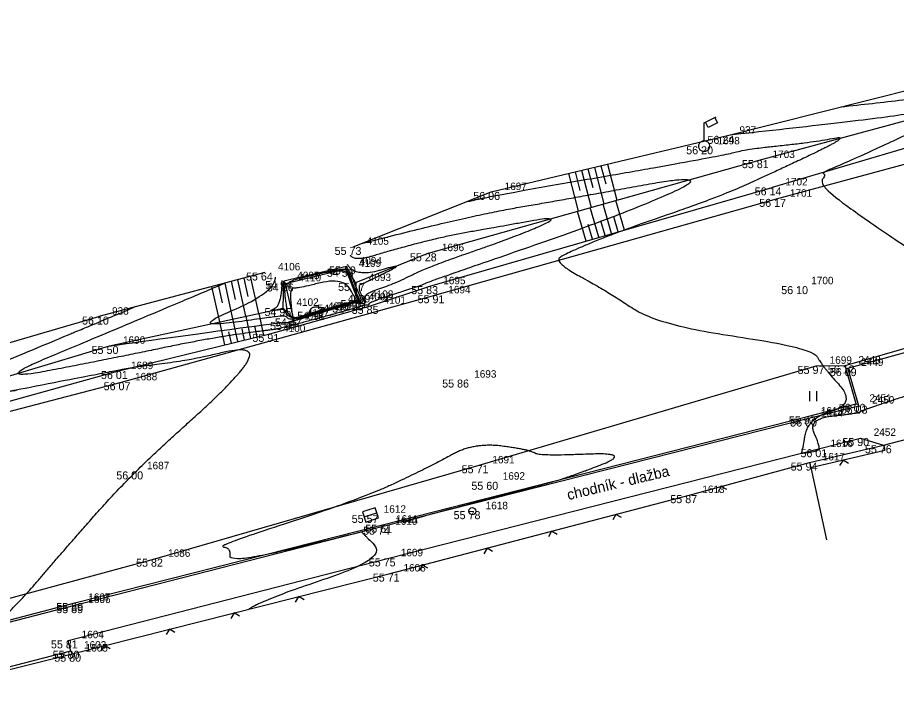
# Model space of a CAD drawing. Extents: x -704017 to -701500, y -1008977 to -1008450.
# Drawn here: x -702683.67 to -702650.74, y -1008782.68 to -1008757.4 of the extents above; entities that cross this region are included whole.
import ezdxf

# ---------------------------------------------------------------- set-up
doc = ezdxf.new("R2010")
doc.units = 0
for name, color, linetype in [('Z_bet_konstrukce', 7, 'Continuous'), ('Z_body', 7, 'Continuous'), ('Z_body_cisla', 7, 'Continuous'), ('Z_body_vysky', 7, 'Continuous'), ('Z_chodnik', 7, 'Continuous'), ('Z_komunikace', 7, 'Continuous'), ('Z_obruby', 7, 'Continuous'), ('Z_oploceni', 7, 'Continuous'), ('Z_popis', 7, 'Continuous'), ('Z_site_znaky_kanalizace', 7, 'Continuous'), ('Z_site_znaky_plynovod', 7, 'Continuous'), ('Z_site_znaky_VO', 7, 'Continuous'), ('Z_teren_hrany_paty', 7, 'Continuous'), ('Z_vrstevnice_hlavni', 7, 'Continuous'), ('Z_vrstevnice_vedlejsi', 7, 'Continuous'), ('Z_vstupy', 7, 'Continuous')]:
    doc.layers.add(name, color=color, linetype=linetype)

# ---------------------------------------------------------------- blocks, each defined once
blk = doc.blocks.new('POINT_DISPLAY')
blk.add_line((0, 0), (0, 0))
blk = doc.blocks.new('Z212')
for p, q in [((-0.17, 0.17), (0, 0)), ((0, 0), (0.17, 0.17))]:
    blk.add_line(p, q)
blk = doc.blocks.new('Z306')
for p, q in [((-0.13, 0.17), (-0.13, -0.2)), ((0.13, 0.17), (0.13, -0.2))]:
    blk.add_line(p, q)
blk = doc.blocks.new('Z13')
for p, q in [((0, 0.88), (0.45, 1.1)), ((0.4, 1.07), (0.5, 0.88)), ((0, 0.2), (0, 0.88)), ((0.15, 0.7), (0.05, 0.9)), ((0.5, 0.88), (0.15, 0.7)), ((-0.2, 0.05), (-0.15, 0.15)), ((-0.2, -0.05), (-0.2, 0.05)), ((-0.15, 0.15), (-0.05, 0.2)), ((-0.05, 0.2), (0.05, 0.2)), ((0.05, 0.2), (0.15, 0.15)), ((0.15, 0.15), (0.2, 0.05)), ((0.2, 0.05), (0.2, -0.05)), ((-0.15, -0.15), (-0.2, -0.05)), ((-0.05, -0.2), (-0.15, -0.15)), ((0.05, -0.2), (-0.05, -0.2)), ((0.15, -0.15), (0.05, -0.2)), ((0.2, -0.05), (0.15, -0.15))]:
    blk.add_line(p, q)
blk = doc.blocks.new('Z38')
for p, q in [((0.25, 0.2), (-0.25, 0.2)), ((-0.25, 0.2), (-0.25, -0.2)), ((-0.25, 0), (0.25, 0)), ((0.25, -0.2), (0.25, 0.2)), ((-0.25, -0.2), (0.25, -0.2))]:
    blk.add_line(p, q)
blk = doc.blocks.new('Z614')
for p, q in [((-0.13, 0.03), (-0.1, 0.08)), ((-0.13, -0.03), (-0.13, 0.03)), ((-0.1, 0.08), (-0.08, 0.1)), ((-0.08, 0.1), (-0.03, 0.13)), ((-0.03, 0.13), (0.03, 0.13)), ((0.03, 0.13), (0.08, 0.1)), ((0.08, 0.1), (0.1, 0.08)), ((0.1, 0.08), (0.13, 0.03)), ((0.13, 0.03), (0.13, -0.03)), ((-0.1, -0.08), (-0.13, -0.03)), ((-0.08, -0.1), (-0.1, -0.08)), ((-0.03, -0.13), (-0.08, -0.1)), ((0.03, -0.13), (-0.03, -0.13)), ((0.08, -0.1), (0.03, -0.13)), ((0.1, -0.08), (0.08, -0.1)), ((0.13, -0.03), (0.1, -0.08))]:
    blk.add_line(p, q)

msp = doc.modelspace()

# ---------------------------------------------------------------- linework, layer by layer
at = {"layer": 'Z_bet_konstrukce'}
for p, q in [((-702673.51, -1008768.8), (-702671.01, -1008768.07)), ((-702671.01, -1008768.07), (-702670.94, -1008768.34)), ((-702673.51, -1008768.8), (-702673.44, -1008769.03))]:
    msp.add_line(p, q, dxfattribs=at)
at = {"layer": 'Z_chodnik'}
for p, q in [((-702652.15, -1008771.94), (-702652.56, -1008770.53)), ((-702654.07, -1008772.42), (-702652.15, -1008771.94)), ((-702670.02, -1008776.47), (-702654.07, -1008772.42)), ((-702653.71, -1008773.57), (-702652.09, -1008773.15)), ((-702652.09, -1008773.15), (-702651.22, -1008773.42)), ((-702669.81, -1008777.66), (-702653.71, -1008773.57)), ((-702681.52, -1008779.41), (-702670.02, -1008776.47)), ((-702681.77, -1008780.73), (-702669.81, -1008777.66)), ((-702686.34, -1008780.66), (-702681.52, -1008779.41)), ((-702681.68, -1008781.12), (-702681.77, -1008780.73)), ((-702685.78, -1008782.18), (-702681.68, -1008781.12)), ((-702681.62, -1008781.23), (-702681.68, -1008781.12))]:
    msp.add_line(p, q, dxfattribs=at)
at = {"layer": 'Z_komunikace'}
for p, q in [((-702655.23, -1008764.19), (-702640.07, -1008760.08)), ((-702668.03, -1008767.8), (-702655.23, -1008764.19)), ((-702679.77, -1008771.06), (-702668.03, -1008767.8)), ((-702652.66, -1008770.43), (-702648.22, -1008769.16)), ((-702666.38, -1008774.17), (-702653.74, -1008770.45)), ((-702653.74, -1008770.45), (-702652.66, -1008770.43)), ((-702689.14, -1008773.5), (-702679.77, -1008771.06)), ((-702678.53, -1008777.67), (-702666.38, -1008774.17)), ((-702687.56, -1008780.13), (-702678.53, -1008777.67))]:
    msp.add_line(p, q, dxfattribs=at)
at = {"layer": 'Z_obruby'}
for p, q in [((-702652.56, -1008770.53), (-702648.67, -1008769.46)), ((-702652.25, -1008771.87), (-702652.66, -1008770.43)), ((-702654.07, -1008772.34), (-702652.25, -1008771.87)), ((-702669.99, -1008776.4), (-702654.07, -1008772.34)), ((-702681.52, -1008779.33), (-702669.99, -1008776.4)), ((-702686.34, -1008780.58), (-702681.52, -1008779.33))]:
    msp.add_line(p, q, dxfattribs=at)
at = {"layer": 'Z_oploceni'}
for p, q in [((-702654, -1008774.07), (-702651.22, -1008773.42)), ((-702651.22, -1008773.42), (-702651.17, -1008773.61)), ((-702653.95, -1008774.26), (-702651.17, -1008773.61)), ((-702658.51, -1008775.29), (-702654, -1008774.07)), ((-702654, -1008774.07), (-702653.95, -1008774.26)), ((-702653.95, -1008774.26), (-702653.36, -1008776.97)), ((-702669.71, -1008778.23), (-702658.51, -1008775.29)), ((-702681.62, -1008781.23), (-702669.71, -1008778.23))]:
    msp.add_line(p, q, dxfattribs=at)
at = {"layer": 'Z_teren_hrany_paty'}
for p, q in [((-702657.12, -1008761.83), (-702639.57, -1008757.4)), ((-702655.88, -1008762.74), (-702639.67, -1008758.35)), ((-702639.01, -1008758.94), (-702655.4, -1008763.76)), ((-702665.92, -1008763.93), (-702657.12, -1008761.83)), ((-702668.27, -1008766.23), (-702655.88, -1008762.74)), ((-702661.57, -1008762.89), (-702661.22, -1008764.24)), ((-702663.03, -1008763.24), (-702662.66, -1008764.65)), ((-702662.78, -1008763.18), (-702662.6, -1008763.88)), ((-702662.54, -1008763.12), (-702662.18, -1008764.51)), ((-702662.3, -1008763.07), (-702662.12, -1008763.76)), ((-702662.05, -1008763.01), (-702661.7, -1008764.38)), ((-702661.81, -1008762.95), (-702661.63, -1008763.63)), ((-702671.09, -1008765.99), (-702665.92, -1008763.93)), ((-702668.22, -1008767.46), (-702655.4, -1008763.76)), ((-702660.93, -1008765.36), (-702661.25, -1008764.25)), ((-702661.89, -1008765.63), (-702662.21, -1008764.52)), ((-702661.41, -1008765.49), (-702661.73, -1008764.39)), ((-702662.37, -1008765.77), (-702662.69, -1008764.66)), ((-702661.17, -1008765.43), (-702661.33, -1008764.87)), ((-702662.13, -1008765.7), (-702662.29, -1008765.15)), ((-702661.65, -1008765.56), (-702661.81, -1008765.01)), ((-702668.27, -1008766.23), (-702671.01, -1008767.34)), ((-702671.35, -1008766.72), (-702673.69, -1008767.27)), ((-702673.63, -1008767.36), (-702671.38, -1008766.81)), ((-702671.38, -1008766.81), (-702671.35, -1008766.72)), ((-702671.38, -1008766.81), (-702670.92, -1008767.98)), ((-702671.01, -1008767.34), (-702671.35, -1008766.72)), ((-702674.41, -1008766.95), (-702680.63, -1008768.6)), ((-702675.43, -1008767.22), (-702675.13, -1008768.59)), ((-702675.19, -1008767.16), (-702675.04, -1008767.85)), ((-702674.95, -1008767.09), (-702674.64, -1008768.48)), ((-702676.4, -1008767.48), (-702676.11, -1008768.8)), ((-702676.15, -1008767.41), (-702676.01, -1008768.08)), ((-702675.91, -1008767.35), (-702675.62, -1008768.69)), ((-702675.67, -1008767.28), (-702675.52, -1008767.96)), ((-702673.72, -1008768.28), (-702673.69, -1008767.27)), ((-702673.63, -1008767.36), (-702673.69, -1008767.27)), ((-702673.33, -1008768.67), (-702673.63, -1008767.36)), ((-702670.92, -1008767.98), (-702671.01, -1008767.34)), ((-702670.45, -1008768.2), (-702668.22, -1008767.46)), ((-702674.22, -1008769.25), (-702670.45, -1008768.2)), ((-702670.92, -1008767.98), (-702673.33, -1008768.67)), ((-702680.22, -1008769.7), (-702673.72, -1008768.28)), ((-702674.44, -1008769.3), (-702674.62, -1008768.48)), ((-702673.33, -1008768.67), (-702673.72, -1008768.28)), ((-702689.43, -1008771.17), (-702680.63, -1008768.6)), ((-702675.9, -1008769.66), (-702676.09, -1008768.8)), ((-702675.42, -1008769.54), (-702675.6, -1008768.69)), ((-702674.93, -1008769.42), (-702675.11, -1008768.58)), ((-702675.66, -1008769.6), (-702675.75, -1008769.17)), ((-702675.17, -1008769.48), (-702675.26, -1008769.06)), ((-702674.69, -1008769.36), (-702674.78, -1008768.95)), ((-702679.92, -1008770.64), (-702674.22, -1008769.25)), ((-702688.98, -1008772.33), (-702680.22, -1008769.7)), ((-702688.82, -1008773.11), (-702679.92, -1008770.64))]:
    msp.add_line(p, q, dxfattribs=at)
at = {"layer": 'Z_vrstevnice_hlavni'}
for points in [[(-702666.86, -1008764.305), (-702666.101, -1008764.107), (-702660.186, -1008763.092), (-702656.884, -1008762.487), (-702656.428, -1008762.338), (-702653.8, -1008762.059), (-702652.34, -1008761.781), (-702655.604, -1008763.327), (-702657.495, -1008764.162), (-702661.19, -1008765.431), (-702663.088, -1008766.219), (-702663.599, -1008766.55), (-702661.588, -1008767.639), (-702659.693, -1008768.918), (-702653.899, -1008769.76), (-702653.524, -1008770.446), (-702652.25, -1008771.87), (-702654.07, -1008772.42), (-702654.272, -1008773.671), (-702654.329, -1008773.727), (-702654.053, -1008773.693), (-702653.751, -1008773.641), (-702653.563, -1008773.532), (-702654.07, -1008772.42), (-702652.136, -1008772.219), (-702652.047, -1008772.104), (-702648.446, -1008770.943), (-702648.305, -1008770.957), (-702647.465, -1008771.9), (-702647.268, -1008772.215), (-702647.277, -1008772.427)], [(-702673.128, -1008767.138), (-702671.359, -1008766.747), (-702671.113, -1008767.192), (-702670.987, -1008767.505), (-702670.748, -1008768.06), (-702670.962, -1008768.022), (-702672.191, -1008768.376), (-702673.425, -1008768.739), (-702673.7, -1008768.33), (-702673.746, -1008768.331), (-702674.311, -1008768.409), (-702673.77, -1008768.184), (-702673.752, -1008767.243)], [(-702687.525, -1008782.68), (-702687.628, -1008782.663), (-702687.511, -1008782.409), (-702686.258, -1008780.875), (-702685.545, -1008780.672), (-702685.055, -1008780.327), (-702684.466, -1008780.125), (-702684.466, -1008780.094), (-702683.981, -1008779.656), (-702683.311, -1008778.972), (-702681.946, -1008777.366), (-702679.32, -1008774.4), (-702675.533, -1008771.027), (-702674.634, -1008769.634), (-702677.342, -1008770.268), (-702679.35, -1008770.501), (-702679.926, -1008770.622), (-702682.94, -1008771.203), (-702688.968, -1008772.388), (-702689.155, -1008772.391), (-702689.011, -1008772.25), (-702687.588, -1008771.708), (-702680.562, -1008768.783), (-702679.278, -1008768.241)]]:
    msp.add_open_spline(points, degree=2, dxfattribs=at)
at = {"layer": 'Z_vrstevnice_vedlejsi'}
for points in [[(-702652.815, -1008760.743), (-702648.327, -1008760.267), (-702643.024, -1008759.258), (-702644.913, -1008760.153), (-702649.44, -1008762.007), (-702648.751, -1008762.164), (-702648.976, -1008762.495), (-702644.741, -1008765.284), (-702643.699, -1008766.374), (-702642.5, -1008767.662), (-702642.564, -1008767.76), (-702643.4, -1008768.055), (-702640.02, -1008769.28), (-702639.841, -1008769.293), (-702639.855, -1008769.324), (-702639.96, -1008769.53), (-702640.699, -1008770.697), (-702640.984, -1008770.85)], [(-702656.954, -1008761.788), (-702651.064, -1008761.163), (-702647.682, -1008760.52), (-702652.196, -1008762.658), (-702653.579, -1008763.224), (-702653.368, -1008763.272), (-702653.714, -1008763.779), (-702647.226, -1008768.053), (-702646.928, -1008768.364), (-702646.586, -1008768.732), (-702646.604, -1008768.76), (-702648.215, -1008769.328), (-702647.964, -1008769.419), (-702644.239, -1008770.04), (-702644.145, -1008770.05), (-702644.165, -1008770.085), (-702645.298, -1008771.374), (-702645.396, -1008771.53), (-702645.789, -1008771.741), (-702645.803, -1008772.093)], [(-702670.777, -1008765.865), (-702666.854, -1008764.844), (-702662.993, -1008764.181), (-702657.283, -1008763.135), (-702661.236, -1008764.88), (-702668.227, -1008767.281), (-702668.558, -1008767.445), (-702670.532, -1008768.074), (-702670.485, -1008768.184), (-702670.637, -1008768.157), (-702671.255, -1008768.358), (-702673.962, -1008769.086), (-702674.137, -1008769.088), (-702676.561, -1008769.426), (-702680.073, -1008770.161), (-702684.783, -1008771.07), (-702680.391, -1008769.242), (-702675.897, -1008767.345)], [(-702680.22, -1008769.7), (-702674.006, -1008768.836), (-702673.558, -1008768.831), (-702673.268, -1008768.753), (-702672.573, -1008768.526), (-702671.117, -1008768.098), (-702671.006, -1008768.066), (-702670.573, -1008768.143), (-702670.738, -1008767.757), (-702669.615, -1008767.4), (-702668.25, -1008766.722), (-702664.978, -1008765.598), (-702663.127, -1008764.781), (-702665.8, -1008765.271), (-702667.607, -1008765.581), (-702669.649, -1008766.113), (-702671.057, -1008766.544), (-702671.201, -1008766.301)], [(-702671.321, -1008766.639), (-702671.021, -1008767.147), (-702669.017, -1008766.533), (-702670.672, -1008767.355), (-702670.944, -1008767.441), (-702670.66, -1008768.101), (-702670.984, -1008768.044), (-702671.654, -1008768.237), (-702673.47, -1008768.771), (-702673.599, -1008768.58), (-702673.876, -1008768.583), (-702677.265, -1008769.055), (-702674.02, -1008767.702), (-702674.009, -1008767.128)], [(-702673.558, -1008768.443), (-702673.674, -1008767.808), (-702673.66, -1008767.315), (-702672.535, -1008767.04), (-702671.371, -1008766.783), (-702671.265, -1008766.975), (-702670.953, -1008767.747), (-702670.836, -1008768.019), (-702670.941, -1008768.001), (-702672.729, -1008768.514), (-702673.38, -1008768.706), (-702673.558, -1008768.443)], [(-702673.354, -1008768.646), (-702673.43, -1008768.233), (-702673.458, -1008767.527), (-702673.188, -1008767.55), (-702671.478, -1008767.132), (-702670.964, -1008767.989), (-702670.969, -1008767.993), (-702671.523, -1008768.153), (-702673.266, -1008768.653), (-702673.335, -1008768.674), (-702673.354, -1008768.646)], [(-702672.731, -1008768.48), (-702672.741, -1008768.225), (-702672.136, -1008768.275), (-702672.196, -1008768.327), (-702672.731, -1008768.48)], [(-702669.172, -1008776.325), (-702669.407, -1008776.314), (-702664.275, -1008774.971), (-702663.025, -1008774.624), (-702660.572, -1008773.676), (-702664.142, -1008773.837), (-702664.435, -1008773.598), (-702666.561, -1008773.314), (-702668.165, -1008774.202), (-702670.798, -1008775.443), (-702676.268, -1008777.211), (-702675.683, -1008777.247), (-702675.755, -1008777.865), (-702670.787, -1008776.661), (-702670.787, -1008776.666), (-702669.81, -1008777.66), (-702674.534, -1008779.23), (-702675.003, -1008779.563)]]:
    msp.add_open_spline(points, degree=2, dxfattribs=at)
at = {"layer": 'Z_vstupy'}
for p, q in [((-702651.22, -1008773.42), (-702648.22, -1008772.64)), ((-702685.75, -1008782.26), (-702681.62, -1008781.23))]:
    msp.add_line(p, q, dxfattribs=at)

# ---------------------------------------------------------------- block references
at = {"layer": 'Z_body'}
for p in [(-702657.12, -1008761.83), (-702657.94, -1008762.22), (-702655.88, -1008762.74), (-702665.92, -1008763.93), (-702655.4, -1008763.76), (-702655.23, -1008764.19), (-702671.09, -1008765.99), (-702668.27, -1008766.23), (-702671.38, -1008766.81), (-702671.35, -1008766.72), (-702674.41, -1008766.95), (-702673.69, -1008767.27), (-702673.63, -1008767.36), (-702671.01, -1008767.34), (-702668.22, -1008767.46), (-702654.43, -1008767.46), (-702668.03, -1008767.8), (-702671.79, -1008768.15), (-702671.01, -1008768.07), (-702670.92, -1008767.98), (-702670.45, -1008768.2), (-702673.72, -1008768.28), (-702672.54, -1008768.42), (-702680.63, -1008768.6), (-702673.51, -1008768.8), (-702673.33, -1008768.67), (-702674.22, -1008769.25), (-702680.22, -1008769.7), (-702653.74, -1008770.45), (-702652.66, -1008770.43), (-702679.92, -1008770.64), (-702652.56, -1008770.53), (-702679.77, -1008771.06), (-702667.06, -1008770.96), (-702652.25, -1008771.87), (-702652.15, -1008771.94), (-702654.07, -1008772.34), (-702654.07, -1008772.42), (-702652.09, -1008773.15), (-702651.22, -1008773.42), (-702653.71, -1008773.57), (-702654, -1008774.07), (-702679.32, -1008774.4), (-702666.38, -1008774.17), (-702665.99, -1008774.79), (-702658.51, -1008775.29), (-702670.45, -1008776.03), (-702666.63, -1008775.89), (-702669.99, -1008776.4), (-702670.02, -1008776.47), (-702678.53, -1008777.67), (-702669.81, -1008777.66), (-702669.71, -1008778.23), (-702681.52, -1008779.33), (-702681.52, -1008779.41), (-702681.77, -1008780.73), (-702681.68, -1008781.12), (-702681.62, -1008781.23)]:
    msp.add_blockref('POINT_DISPLAY', p, dxfattribs=at)
at = {"layer": 'Z_oploceni'}
for p, rotation in [((-702652.74, -1008773.98), -166.80000000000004), ((-702657.3, -1008774.96), -164.90000000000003), ((-702661.25, -1008776.01), -165.3), ((-702663.66, -1008776.64), -165.3), ((-702666.08, -1008777.28), -165.3), ((-702668.5, -1008777.91), -165.3), ((-702673.14, -1008779.09), -165.9), ((-702675.56, -1008779.7), -165.9), ((-702677.98, -1008780.31), -165.9), ((-702680.41, -1008780.92), -165.9)]:
    msp.add_blockref('Z212', p, dxfattribs=dict(at, rotation=rotation))
at = {"layer": 'Z_popis'}
msp.add_blockref('Z306', (-702653.86, -1008771.57), dxfattribs=at)
at = {"layer": 'Z_site_znaky_kanalizace', "rotation": 18}
msp.add_blockref('Z38', (-702670.45, -1008776.03), dxfattribs=at)
at = {"layer": 'Z_site_znaky_plynovod', "rotation": 10.799999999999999}
msp.add_blockref('Z614', (-702666.63, -1008775.89), dxfattribs=at)
at = {"layer": 'Z_site_znaky_VO'}
msp.add_blockref('Z13', (-702657.94, -1008762.22), dxfattribs=at)

# ---------------------------------------------------------------- texts
at = {"layer": 'Z_body_cisla'}
for s, p in [('937', (-702656.62, -1008761.75)), ('1698', (-702657.44, -1008762.15)), ('1703', (-702655.38, -1008762.66)), ('1697', (-702665.42, -1008763.86)), ('1702', (-702654.9, -1008763.69)), ('1701', (-702654.73, -1008764.11)), ('4105', (-702670.59, -1008765.91)), ('1696', (-702667.77, -1008766.15)), ('4109', (-702670.88, -1008766.74)), ('4094', (-702670.85, -1008766.65)), ('4106', (-702673.91, -1008766.87)), ('4095', (-702673.19, -1008767.2)), ('4110', (-702673.13, -1008767.28)), ('4093', (-702670.51, -1008767.27)), ('1695', (-702667.72, -1008767.39)), ('1700', (-702653.93, -1008767.39)), ('1694', (-702667.53, -1008767.73)), ('4099', (-702671.29, -1008768.07)), ('4092', (-702670.51, -1008767.99)), ('4108', (-702670.42, -1008767.9)), ('4101', (-702669.95, -1008768.12)), ('4102', (-702673.22, -1008768.2)), ('4098', (-702672.04, -1008768.35)), ('938', (-702680.13, -1008768.53)), ('4091', (-702673.01, -1008768.73)), ('4107', (-702672.83, -1008768.6)), ('4100', (-702673.72, -1008769.18)), ('1690', (-702679.72, -1008769.62)), ('1699', (-702653.24, -1008770.37)), ('2448', (-702652.16, -1008770.36)), ('2449', (-702652.06, -1008770.45)), ('1689', (-702679.42, -1008770.57)), ('1688', (-702679.27, -1008770.99)), ('1693', (-702666.56, -1008770.89)), ('2451', (-702651.75, -1008771.79)), ('2450', (-702651.65, -1008771.86)), ('1615', (-702653.57, -1008772.27)), ('1614', (-702653.57, -1008772.35)), ('2452', (-702651.59, -1008773.07)), ('1616', (-702653.21, -1008773.49)), ('1617', (-702653.5, -1008773.99)), ('1687', (-702678.82, -1008774.32)), ('1691', (-702665.88, -1008774.1)), ('1692', (-702665.49, -1008774.71)), ('1613', (-702658.01, -1008775.21)), ('1612', (-702669.95, -1008775.95)), ('1618', (-702666.13, -1008775.82)), ('1610', (-702669.52, -1008776.4)), ('1611', (-702669.49, -1008776.32)), ('1686', (-702678.03, -1008777.6)), ('1609', (-702669.31, -1008777.58)), ('1608', (-702669.21, -1008778.15)), ('1607', (-702681.02, -1008779.25)), ('1606', (-702681.02, -1008779.33)), ('1604', (-702681.27, -1008780.65)), ('1603', (-702681.18, -1008781.04)), ('1605', (-702681.12, -1008781.15))]:
    msp.add_text(s, height=0.28, dxfattribs=at).set_placement(p)
at = {"layer": 'Z_body_vysky'}
for s, p in [('56 24', (-702657.82, -1008762.13)), ('56 20', (-702658.615, -1008762.52)), ('55 81', (-702656.53, -1008763.04)), ('56 06', (-702666.595, -1008764.23)), ('56 14', (-702656.05, -1008764.06)), ('56 17', (-702655.88, -1008764.49)), ('55 73', (-702671.79, -1008766.29)), ('55 28', (-702668.97, -1008766.53)), ('54 56', (-702672.08, -1008767.11)), ('55 19', (-702672, -1008767.02)), ('55 64', (-702675.11, -1008767.25)), ('54 94', (-702674.39, -1008767.57)), ('54 56', (-702674.33, -1008767.66)), ('55 17', (-702671.66, -1008767.64)), ('55 83', (-702668.92, -1008767.76)), ('56 10', (-702655.055, -1008767.76)), ('55 91', (-702668.68, -1008768.1)), ('54 31', (-702672.44, -1008768.45)), ('55 55', (-702671.71, -1008768.37)), ('54 51', (-702671.57, -1008768.28)), ('55 85', (-702671.15, -1008768.5)), ('54 95', (-702674.42, -1008768.58)), ('54 18', (-702673.19, -1008768.72)), ('56 10', (-702681.255, -1008768.9)), ('55 47', (-702674.21, -1008769.1)), ('54 47', (-702674.03, -1008768.97)), ('55 91', (-702674.87, -1008769.55)), ('55 50', (-702680.895, -1008770)), ('55 97', (-702654.44, -1008770.75)), ('56 12', (-702653.31, -1008770.73)), ('56 01', (-702680.545, -1008770.94)), ('56 09', (-702653.235, -1008770.83)), ('56 07', (-702680.445, -1008771.36)), ('55 86', (-702667.76, -1008771.26)), ('56 00', (-702652.9, -1008772.17)), ('56 03', (-702652.825, -1008772.24)), ('55 93', (-702654.77, -1008772.64)), ('56 00', (-702654.72, -1008772.72)), ('55 90', (-702652.765, -1008773.45)), ('55 76', (-702651.92, -1008773.72)), ('56 01', (-702654.335, -1008773.87)), ('55 94', (-702654.7, -1008774.37)), ('56 00', (-702679.97, -1008774.7)), ('55 71', (-702667.03, -1008774.47)), ('55 60', (-702666.665, -1008775.09)), ('55 87', (-702659.21, -1008775.59)), ('55 57', (-702671.15, -1008776.33)), ('55 78', (-702667.33, -1008776.19)), ('55 61', (-702670.64, -1008776.7)), ('55 74', (-702670.72, -1008776.77)), ('55 82', (-702679.23, -1008777.97)), ('55 75', (-702670.51, -1008777.96)), ('55 71', (-702670.36, -1008778.53)), ('55 89', (-702682.22, -1008779.63)), ('55 89', (-702682.22, -1008779.71)), ('55 81', (-702682.42, -1008781.03)), ('55 80', (-702682.355, -1008781.42)), ('55 80', (-702682.295, -1008781.53))]:
    msp.add_text(s, height=0.3, dxfattribs=at).set_placement(p)
at = {"layer": 'Z_popis'}
msp.add_text('chodník - dlažba', height=0.4, rotation=13.5, dxfattribs=at).set_placement((-702663.03, -1008775.48))

doc.saveas('drawing.dxf')
